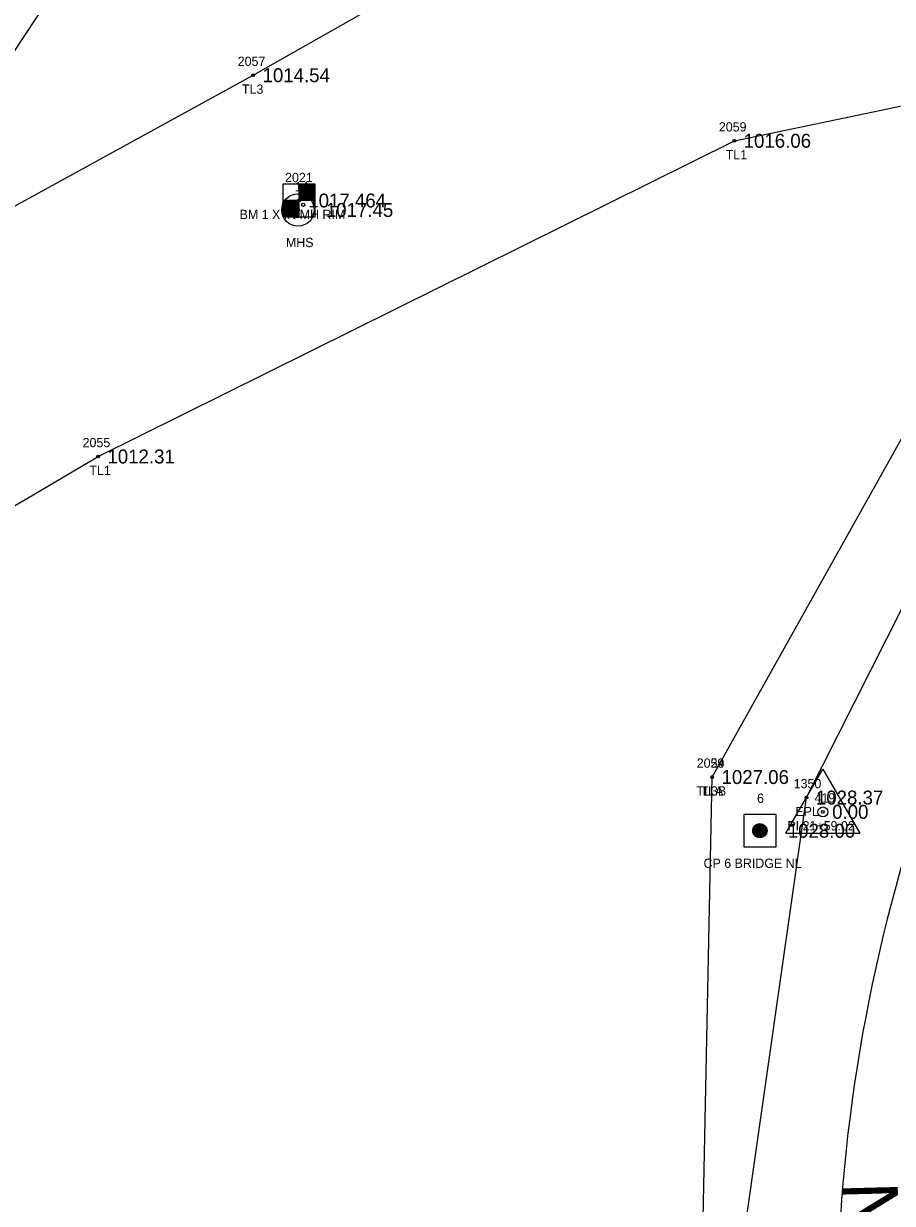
# Model space of a CAD drawing. Extents: x 1578957 to 1581675, y 1115963 to 1120391.
# Drawn here: x 1579963.3 to 1580056.7, y 1117455.7 to 1117582.7 of the extents above; entities that cross this region are included whole.
import ezdxf

# ---------------------------------------------------------------- set-up
doc = ezdxf.new("R2010")
doc.units = 0
for name, color, linetype in [('RD_EX_DR_Inlet', 7, 'Continuous'), ('RD_EX_H2O', 7, 'Continuous'), ('RD_EX_Road', 7, 'Continuous'), ('RD_EX_Road_txCode', 7, 'Continuous'), ('RD_EX_TX_Road_ELEV', 7, 'Continuous'), ('RD_EX_TX_UT_ELEV', 7, 'Continuous'), ('RD_EX_TX_VEG_ELEV', 7, 'Continuous'), ('RD_EX_UT_txCode', 7, 'Continuous'), ('RD_EX_VEG', 7, 'Continuous'), ('RD_EX_VEG_txCode', 7, 'Continuous'), ('RD_HC_Cl', 7, 'Continuous'), ('RD_HC_Data', 7, 'Continuous'), ('RD_HC_Survey', 7, 'Continuous'), ('RD_HC_Survey_ELEV', 7, 'Continuous'), ('RD_HC_Survey_txCode', 7, 'Continuous'), ('RD_HC_txCode', 7, 'Continuous'), ('RD_SMD_Locator', 7, 'Continuous')]:
    doc.layers.add(name, color=color, linetype=linetype)

msp = doc.modelspace()

# ---------------------------------------------------------------- linework, layer by layer
at = {"layer": 'RD_EX_DR_Inlet'}
for centre, radius in [((1579992.79, 1117562.63), 1.75), ((1579992.12, 1117563.26), 0.175), ((1579993.35, 1117563.19), 0.175), ((1579992.7, 1117561.96), 0.175)]:
    msp.add_circle(centre, radius, dxfattribs=at)
at = {"layer": 'RD_EX_H2O'}
msp.add_lwpolyline([(1580114.36, 1117618.23), (1580111.13, 1117616.52), (1580060.93, 1117607.76), (1580010.2, 1117604.68), (1579972.14, 1117594.78), (1579950.86, 1117562.52), (1579900.72, 1117528.16), (1579847.19, 1117508.78), (1579806.56, 1117495.65), (1579759.78, 1117473.3), (1579735.67, 1117463.5), (1579695.13, 1117482.24)], dxfattribs=at)
at = {"layer": 'RD_EX_Road'}
msp.add_lwpolyline([(1580039.47, 1117383.8), (1580042.06, 1117389.17), (1580041.45, 1117399.65), (1580040.43, 1117449.77), (1580047.51, 1117499.37), (1580069.95, 1117543.83), (1580097.6, 1117585.15), (1580107.79, 1117601.26), (1580114.64, 1117617.95)], dxfattribs=at)
at = {"layer": 'RD_EX_VEG'}
msp.add_line((1580037.36, 1117501.58), (1580080.38, 1117578.58), dxfattribs=at)
for points in [[(1579862.33, 1117508.14), (1579987.98, 1117577.14), (1580030.01, 1117601.02), (1580092.8, 1117606.94), (1580099.44, 1117660.22), (1579997.24, 1117695.78), (1579947.95, 1117691.88), (1579838.07, 1117719.77), (1579796.8, 1117753), (1579780.49, 1117738.53), (1579705.63, 1117750.62)], [(1579816.83, 1117422.38), (1579804.74, 1117440.56), (1579835.79, 1117461.67), (1579872.53, 1117477.86), (1579971.29, 1117536.09), (1580039.74, 1117570.08), (1580080.38, 1117578.58)], [(1579816.83, 1117422.38), (1579865.4, 1117413.03), (1579908.18, 1117404.27), (1580035.12, 1117392.42), (1580037.36, 1117501.58)]]:
    msp.add_lwpolyline(points, dxfattribs=at)
at = {"layer": 'RD_HC_Cl'}
msp.add_arc((1580229.76, 1117442.52), 179, 144.4316, 181.4941, dxfattribs=at)
at = {"layer": 'RD_HC_Data'}
for p, q in [((1580045.29, 1117495.54), (1580049.26, 1117502.42)), ((1580049.26, 1117502.42), (1580053.23, 1117495.54)), ((1580045.29, 1117495.54), (1580053.23, 1117495.54))]:
    msp.add_line(p, q, dxfattribs=at)
msp.add_circle((1580049.26, 1117497.83), 0.529, dxfattribs=at)
at = {"layer": 'RD_HC_Survey'}
for p, q in [((1579992.9, 1117565.4), (1579992.9, 1117561.9)), ((1579992.92, 1117565.4), (1579992.92, 1117563.65)), ((1579992.94, 1117565.4), (1579992.94, 1117563.65)), ((1579992.97, 1117565.4), (1579992.97, 1117563.65)), ((1579992.99, 1117565.4), (1579992.99, 1117563.65)), ((1579993.02, 1117565.4), (1579993.02, 1117563.65)), ((1579993.04, 1117565.4), (1579993.04, 1117563.65)), ((1579993.07, 1117565.4), (1579993.07, 1117563.65)), ((1579993.09, 1117565.4), (1579993.09, 1117563.65)), ((1579993.11, 1117565.4), (1579993.11, 1117563.65)), ((1579993.14, 1117565.4), (1579993.14, 1117563.65)), ((1579993.16, 1117565.4), (1579993.16, 1117563.65)), ((1579993.19, 1117565.4), (1579993.19, 1117563.65)), ((1579993.21, 1117565.4), (1579993.21, 1117563.65)), ((1579993.24, 1117565.4), (1579993.24, 1117563.65)), ((1579993.26, 1117565.4), (1579993.26, 1117563.65)), ((1579993.29, 1117565.4), (1579993.29, 1117563.65)), ((1579993.31, 1117565.4), (1579993.31, 1117563.65)), ((1579993.34, 1117565.4), (1579993.34, 1117563.65)), ((1579993.36, 1117565.4), (1579993.36, 1117563.65)), ((1579993.39, 1117565.4), (1579993.39, 1117563.65)), ((1579993.41, 1117565.4), (1579993.41, 1117563.65)), ((1579993.44, 1117565.4), (1579993.44, 1117563.65)), ((1579993.46, 1117565.4), (1579993.46, 1117563.65)), ((1579993.49, 1117565.4), (1579993.49, 1117563.65)), ((1579993.51, 1117565.4), (1579993.51, 1117563.65)), ((1579993.54, 1117565.4), (1579993.54, 1117563.65)), ((1579993.56, 1117565.4), (1579993.56, 1117563.65)), ((1579993.58, 1117565.4), (1579993.58, 1117563.65)), ((1579993.61, 1117565.4), (1579993.61, 1117563.65)), ((1579993.63, 1117565.4), (1579993.63, 1117563.65)), ((1579993.66, 1117565.4), (1579993.66, 1117563.65)), ((1579993.68, 1117565.4), (1579993.68, 1117563.65)), ((1579993.71, 1117565.4), (1579993.71, 1117563.65)), ((1579993.73, 1117565.4), (1579993.73, 1117563.65)), ((1579993.76, 1117565.4), (1579993.76, 1117563.65)), ((1579993.78, 1117565.4), (1579993.78, 1117563.65)), ((1579993.81, 1117565.4), (1579993.81, 1117563.65)), ((1579993.83, 1117565.4), (1579993.83, 1117563.65)), ((1579993.86, 1117565.4), (1579993.86, 1117563.65)), ((1579993.88, 1117565.4), (1579993.88, 1117563.65)), ((1579993.91, 1117565.4), (1579993.91, 1117563.65)), ((1579993.93, 1117565.4), (1579993.93, 1117563.65)), ((1579993.96, 1117565.4), (1579993.96, 1117563.65)), ((1579993.98, 1117565.4), (1579993.98, 1117563.65)), ((1579994.01, 1117565.4), (1579994.01, 1117563.65)), ((1579994.03, 1117565.4), (1579994.03, 1117563.65)), ((1579994.06, 1117565.4), (1579994.06, 1117563.65)), ((1579994.08, 1117565.4), (1579994.08, 1117563.65)), ((1579994.1, 1117565.4), (1579994.1, 1117563.65)), ((1579994.13, 1117565.4), (1579994.13, 1117563.65)), ((1579994.15, 1117565.4), (1579994.15, 1117563.65)), ((1579994.18, 1117565.4), (1579994.18, 1117563.65)), ((1579994.2, 1117565.4), (1579994.2, 1117563.65)), ((1579994.23, 1117565.4), (1579994.23, 1117563.65)), ((1579994.25, 1117565.4), (1579994.25, 1117563.65)), ((1579994.28, 1117565.4), (1579994.28, 1117563.65)), ((1579994.3, 1117565.4), (1579994.3, 1117563.65)), ((1579994.33, 1117565.4), (1579994.33, 1117563.65)), ((1579994.35, 1117565.4), (1579994.35, 1117563.65)), ((1579994.38, 1117565.4), (1579994.38, 1117563.65)), ((1579994.4, 1117565.4), (1579994.4, 1117563.65)), ((1579994.43, 1117565.4), (1579994.43, 1117563.65)), ((1579994.45, 1117565.4), (1579994.45, 1117563.65)), ((1579994.48, 1117565.4), (1579994.48, 1117563.65)), ((1579994.5, 1117565.4), (1579994.5, 1117563.65)), ((1579994.53, 1117565.4), (1579994.53, 1117563.65)), ((1579994.55, 1117565.4), (1579994.55, 1117563.65)), ((1579994.57, 1117565.4), (1579994.57, 1117563.65)), ((1579994.6, 1117565.4), (1579994.6, 1117563.65)), ((1579994.62, 1117565.4), (1579994.62, 1117563.65)), ((1579994.65, 1117563.65), (1579991.15, 1117563.65)), ((1579991.15, 1117563.65), (1579991.15, 1117561.9)), ((1579991.17, 1117563.65), (1579991.17, 1117561.9)), ((1579991.2, 1117563.65), (1579991.2, 1117561.9)), ((1579991.22, 1117563.65), (1579991.22, 1117561.9)), ((1579991.25, 1117563.65), (1579991.25, 1117561.9)), ((1579991.27, 1117563.65), (1579991.27, 1117561.9)), ((1579991.3, 1117563.65), (1579991.3, 1117561.9)), ((1579991.32, 1117563.65), (1579991.32, 1117561.9)), ((1579991.35, 1117563.65), (1579991.35, 1117561.9)), ((1579991.37, 1117563.65), (1579991.37, 1117561.9)), ((1579991.4, 1117563.65), (1579991.4, 1117561.9)), ((1579991.42, 1117563.65), (1579991.42, 1117561.9)), ((1579991.45, 1117563.65), (1579991.45, 1117561.9)), ((1579991.47, 1117563.65), (1579991.47, 1117561.9)), ((1579991.5, 1117563.65), (1579991.5, 1117561.9)), ((1579991.52, 1117563.65), (1579991.52, 1117561.9)), ((1579991.55, 1117563.65), (1579991.55, 1117561.9)), ((1579991.57, 1117563.65), (1579991.57, 1117561.9)), ((1579991.59, 1117563.65), (1579991.59, 1117561.9)), ((1579991.62, 1117563.65), (1579991.62, 1117561.9)), ((1579991.64, 1117563.65), (1579991.64, 1117561.9)), ((1579991.67, 1117563.65), (1579991.67, 1117561.9)), ((1579991.69, 1117563.65), (1579991.69, 1117561.9)), ((1579991.72, 1117563.65), (1579991.72, 1117561.9)), ((1579991.74, 1117563.65), (1579991.74, 1117561.9)), ((1579991.77, 1117563.65), (1579991.77, 1117561.9)), ((1579991.79, 1117563.65), (1579991.79, 1117561.9)), ((1579991.82, 1117563.65), (1579991.82, 1117561.9)), ((1579991.84, 1117563.65), (1579991.84, 1117561.9)), ((1579991.87, 1117563.65), (1579991.87, 1117561.9)), ((1579991.89, 1117563.65), (1579991.89, 1117561.9)), ((1579991.92, 1117563.65), (1579991.92, 1117561.9)), ((1579991.94, 1117563.65), (1579991.94, 1117561.9)), ((1579991.97, 1117563.65), (1579991.97, 1117561.9)), ((1579991.99, 1117563.65), (1579991.99, 1117561.9)), ((1579992.02, 1117563.65), (1579992.02, 1117561.9)), ((1579992.04, 1117563.65), (1579992.04, 1117561.9)), ((1579992.06, 1117563.65), (1579992.06, 1117561.9)), ((1579992.09, 1117563.65), (1579992.09, 1117561.9)), ((1579992.11, 1117563.65), (1579992.11, 1117561.9)), ((1579992.14, 1117563.65), (1579992.14, 1117561.9)), ((1579992.16, 1117563.65), (1579992.16, 1117561.9)), ((1579992.19, 1117563.65), (1579992.19, 1117561.9)), ((1579992.21, 1117563.65), (1579992.21, 1117561.9)), ((1579992.24, 1117563.65), (1579992.24, 1117561.9)), ((1579992.26, 1117563.65), (1579992.26, 1117561.9)), ((1579992.29, 1117563.65), (1579992.29, 1117561.9)), ((1579992.31, 1117563.65), (1579992.31, 1117561.9)), ((1579992.34, 1117563.65), (1579992.34, 1117561.9)), ((1579992.36, 1117563.65), (1579992.36, 1117561.9)), ((1579992.39, 1117563.65), (1579992.39, 1117561.9)), ((1579992.41, 1117563.65), (1579992.41, 1117561.9)), ((1579992.44, 1117563.65), (1579992.44, 1117561.9)), ((1579992.46, 1117563.65), (1579992.46, 1117561.9)), ((1579992.49, 1117563.65), (1579992.49, 1117561.9)), ((1579992.51, 1117563.65), (1579992.51, 1117561.9)), ((1579992.54, 1117563.65), (1579992.54, 1117561.9)), ((1579992.56, 1117563.65), (1579992.56, 1117561.9)), ((1579992.58, 1117563.65), (1579992.58, 1117561.9)), ((1579992.61, 1117563.65), (1579992.61, 1117561.9)), ((1579992.63, 1117563.65), (1579992.63, 1117561.9)), ((1579992.66, 1117563.65), (1579992.66, 1117561.9)), ((1579992.68, 1117563.65), (1579992.68, 1117561.9)), ((1579992.71, 1117563.65), (1579992.71, 1117561.9)), ((1579992.73, 1117563.65), (1579992.73, 1117561.9)), ((1579992.76, 1117563.65), (1579992.76, 1117561.9)), ((1579992.78, 1117563.65), (1579992.78, 1117561.9)), ((1579992.81, 1117563.65), (1579992.81, 1117561.9)), ((1579992.83, 1117563.65), (1579992.83, 1117561.9)), ((1579992.86, 1117563.65), (1579992.86, 1117561.9)), ((1579992.88, 1117563.65), (1579992.88, 1117561.9)), ((1580041.74, 1117495.62), (1580041.74, 1117495.98)), ((1580041.76, 1117495.54), (1580041.76, 1117496.07)), ((1580041.79, 1117495.48), (1580041.79, 1117496.13)), ((1580041.81, 1117495.43), (1580041.81, 1117496.17)), ((1580041.84, 1117495.39), (1580041.84, 1117496.22)), ((1580041.86, 1117495.35), (1580041.86, 1117496.25)), ((1580041.89, 1117495.32), (1580041.89, 1117496.29)), ((1580041.91, 1117495.29), (1580041.91, 1117496.32)), ((1580041.94, 1117495.27), (1580041.94, 1117496.34)), ((1580041.96, 1117495.24), (1580041.96, 1117496.37)), ((1580041.99, 1117495.22), (1580041.99, 1117496.39)), ((1580042.01, 1117495.2), (1580042.01, 1117496.41)), ((1580042.04, 1117495.18), (1580042.04, 1117496.43)), ((1580042.06, 1117495.16), (1580042.06, 1117496.44)), ((1580042.09, 1117495.15), (1580042.09, 1117496.46)), ((1580042.11, 1117495.13), (1580042.11, 1117496.47)), ((1580042.14, 1117495.12), (1580042.14, 1117496.49)), ((1580042.16, 1117495.11), (1580042.16, 1117496.5)), ((1580042.18, 1117495.1), (1580042.18, 1117496.51)), ((1580042.21, 1117495.09), (1580042.21, 1117496.52)), ((1580042.23, 1117495.08), (1580042.23, 1117496.53)), ((1580042.26, 1117495.07), (1580042.26, 1117496.54)), ((1580042.28, 1117495.06), (1580042.28, 1117496.55)), ((1580042.31, 1117495.06), (1580042.31, 1117496.55)), ((1580042.33, 1117495.05), (1580042.33, 1117496.56)), ((1580042.36, 1117495.05), (1580042.36, 1117496.56)), ((1580042.38, 1117495.04), (1580042.38, 1117496.57)), ((1580042.41, 1117495.04), (1580042.41, 1117496.57)), ((1580042.43, 1117495.04), (1580042.43, 1117496.57)), ((1580042.46, 1117495.03), (1580042.46, 1117496.57)), ((1580042.48, 1117495.03), (1580042.48, 1117496.57)), ((1580042.51, 1117495.03), (1580042.51, 1117496.57)), ((1580042.53, 1117495.04), (1580042.53, 1117496.57)), ((1580042.56, 1117495.04), (1580042.56, 1117496.57)), ((1580042.58, 1117495.04), (1580042.58, 1117496.57)), ((1580042.61, 1117495.04), (1580042.61, 1117496.56)), ((1580042.63, 1117495.05), (1580042.63, 1117496.56)), ((1580042.66, 1117495.05), (1580042.66, 1117496.55)), ((1580042.68, 1117495.06), (1580042.68, 1117496.55)), ((1580042.7, 1117495.07), (1580042.7, 1117496.54)), ((1580042.73, 1117495.07), (1580042.73, 1117496.53)), ((1580042.75, 1117495.08), (1580042.75, 1117496.53)), ((1580042.78, 1117495.09), (1580042.78, 1117496.52)), ((1580042.8, 1117495.1), (1580042.8, 1117496.51)), ((1580042.83, 1117495.11), (1580042.83, 1117496.49)), ((1580042.85, 1117495.13), (1580042.85, 1117496.48)), ((1580042.88, 1117495.14), (1580042.88, 1117496.47)), ((1580042.9, 1117495.16), (1580042.9, 1117496.45)), ((1580042.93, 1117495.17), (1580042.93, 1117496.44)), ((1580042.95, 1117495.19), (1580042.95, 1117496.42)), ((1580042.98, 1117495.21), (1580042.98, 1117496.4)), ((1580043, 1117495.23), (1580043, 1117496.38)), ((1580043.03, 1117495.25), (1580043.03, 1117496.35)), ((1580043.05, 1117495.28), (1580043.05, 1117496.33)), ((1580043.08, 1117495.31), (1580043.08, 1117496.3)), ((1580043.1, 1117495.34), (1580043.1, 1117496.27)), ((1580043.13, 1117495.37), (1580043.13, 1117496.23)), ((1580043.15, 1117495.41), (1580043.15, 1117496.2)), ((1580043.17, 1117495.46), (1580043.17, 1117496.15)), ((1580043.2, 1117495.51), (1580043.2, 1117496.1)), ((1580043.22, 1117495.58), (1580043.22, 1117496.03)), ((1580043.25, 1117495.69), (1580043.25, 1117495.92))]:
    msp.add_line(p, q, dxfattribs=at)
for points in [[(1579994.65, 1117565.4), (1579991.15, 1117565.4), (1579991.15, 1117561.9), (1579994.65, 1117561.9)], [(1580044.24, 1117497.55), (1580040.74, 1117497.55), (1580040.74, 1117494.05), (1580044.24, 1117494.05)]]:
    msp.add_lwpolyline(points, close=True, dxfattribs=at)
msp.add_circle((1580042.49, 1117495.8), 0.769, dxfattribs=at)
at = {"layer": 'RD_SMD_Locator'}
for centre in [(1579987.98, 1117577.14), (1580039.74, 1117570.08), (1579992.9, 1117563.65), (1579992.79, 1117562.63), (1579971.29, 1117536.09), (1580037.36, 1117501.58), (1580037.36, 1117501.58), (1580047.51, 1117499.37), (1580049.26, 1117497.83), (1580042.49, 1117495.8)]:
    msp.add_circle(centre, 0.15, dxfattribs=at)

# ---------------------------------------------------------------- texts
at = {"layer": 'RD_EX_Road_txCode'}
for s, p in [('1350', (1580046.12, 1117500.37)), ('EPL', (1580046.3, 1117497.37))]:
    msp.add_text(s, height=1, dxfattribs=at).set_placement(p)
at = {"layer": 'RD_EX_TX_Road_ELEV'}
msp.add_text('1028.37', height=1.5, dxfattribs=at).set_placement((1580048.51, 1117498.62))
at = {"layer": 'RD_EX_TX_UT_ELEV'}
msp.add_text('1017.45', height=1.5, dxfattribs=at).set_placement((1579995.79, 1117561.88))
at = {"layer": 'RD_EX_TX_VEG_ELEV'}
for s, p in [('1014.54', (1579988.98, 1117576.39)), ('1016.06', (1580040.74, 1117569.33)), ('1012.31', (1579972.29, 1117535.34)), ('1027.06', (1580038.36, 1117500.83)), ('1027.06', (1580038.36, 1117500.83))]:
    msp.add_text(s, height=1.5, dxfattribs=at).set_placement(p)
at = {"layer": 'RD_EX_UT_txCode'}
for s, p in [('2021', (1579991.4, 1117565.63)), ('MHS', (1579991.49, 1117558.63))]:
    msp.add_text(s, height=1, dxfattribs=at).set_placement(p)
at = {"layer": 'RD_EX_VEG_txCode'}
for s, p in [('2057', (1579986.31, 1117578.14)), ('TL3', (1579986.76, 1117575.14)), ('2059', (1580038.07, 1117571.08)), ('TL1', (1580038.81, 1117568.08)), ('2055', (1579969.62, 1117537.09)), ('TL1', (1579970.35, 1117534.09)), ('2029', (1580035.69, 1117502.58)), ('2054', (1580035.69, 1117502.58)), ('TL3B', (1580035.66, 1117499.58)), ('TLA', (1580036.1, 1117499.58))]:
    msp.add_text(s, height=1, dxfattribs=at).set_placement(p)
at = {"layer": 'RD_HC_Data'}
for s, rotation, p in [('N 33%%d 05\' 13" E', 56.913, (1579941, 1117562.54)), ('N 1%%d 29\' 39" W', 271.4941, (1580051.3, 1117457.95))]:
    msp.add_text(s, height=6, rotation=rotation, dxfattribs=at).set_placement(p)
at = {"layer": 'RD_HC_Survey_ELEV'}
for s, p in [('1017.464', (1579993.9, 1117562.9)), ('0.00', (1580050.26, 1117497.08)), ('1028.00', (1580045.49, 1117495.05))]:
    msp.add_text(s, height=1.5, dxfattribs=at).set_placement(p)
at = {"layer": 'RD_HC_Survey_txCode'}
for s, p in [('14', (1579992.45, 1117564.65)), ('BM 1 X IN MH RIM', (1579986.51, 1117561.65)), ('6', (1580042.18, 1117498.8)), ('CP 6 BRIDGE NL', (1580036.42, 1117491.8))]:
    msp.add_text(s, height=1, dxfattribs=at).set_placement(p)
at = {"layer": 'RD_HC_txCode'}
for s, p in [('419', (1580048.36, 1117498.83)), ('PI 21+59.02', (1580045.44, 1117495.83))]:
    msp.add_text(s, height=1, dxfattribs=at).set_placement(p)

doc.saveas('drawing.dxf')
